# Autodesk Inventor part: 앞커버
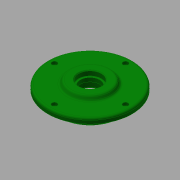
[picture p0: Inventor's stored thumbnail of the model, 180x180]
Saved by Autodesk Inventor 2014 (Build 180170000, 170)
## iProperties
Created: 2016-11
Part Number: 앞커버
Material: 일반
Document SubType Name: Modeling
Designer: mduedu
Density: 1 g/cm^3
Appearance: 진녹색
Mass: 188.69 g
Surface Area: 365.029 cm^2
Volume: 188.69 cm^3
Author: mduedu
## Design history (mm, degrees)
sketch "스케치1"
  geometry: L1 (28.5, -17.5)-(28.5, -30); L2 (28.5, -30)-(22.5, -33.464); L3 (22.5, -33.464)-(22.5, -65); L4 (22.5, -65)-(14.5, -65); L5 (14.5, -65)-(14.5, -47.5); L6 (14.5, -47.5)-(0, -47.5); L7 (0, -47.5)-(0, -23.5); L8 (0, 0)-(28.5, 0); L9 (14.5, -23.5)-(14.5, -15); L10 (14.5, -15)-(20.5, -15); L11 (20.5, -15)-(20.5, -17.5); L12 (0, -23.5)-(14.5, -23.5); L13 (20.5, -17.5)-(28.5, -17.5)
  constraints: 26 end point, 8 parallel, 3 perpendicular, 2 horizontal, 2 vertical alignment, 1 collinear
  dimensions: "d0" = 14.5 distance of L5.end L6.end; "d2" = 8 distance of L3.end L4.end; "d3" = 6 distance between parallel lines of L1 L3; "d4" = 120 deg angle of L3 L2; "d5" = 8 distance of L11.end L1.start; "d6" = 60 diameter of L1.end L8; "d7" = 30 diameter of L10 L8; "d8" = 47 diameter of L12 L8; "d9" = 35 diameter of L13 L8; "d10" = 95 diameter of L6 L8; "d11" = 130 diameter of L4 L8
revolve "회전1" sketch "스케치1" stored, may be unused: angle "d12" = 90 deg
fillet "모깎기1" dims "d13" = 0.5
fillet "모깎기2" dims "d14" = 3
chamfer "모따기1" distance "d15" = 1; stored, may be unused: second distance "d16" = 2, angle "d17" = 45 deg
fillet "모깎기3" dims "d18" = 0.3
sketch "스케치2" dims "d19" = 110
  geometry: 6 further points
  constraints: 2 vertical alignment, 1 coincident, 7 other
  dimensions: "d22" = 360 deg dimension on point (0, 0) point (0, 55) (derived)
sketch "스케치3"
  geometry: 4 further points
  constraints: 4 other
hole "구멍1" sketch "스케치3" at (0, 55), (-55, 0), (55, 0), (0, -55) diameter "d24" = 4.5; stored, may be unused: countersink angle "d28" = 90 deg, drill point angle "d30" = 0 deg; dims "d25" = 6, "d26" = 8, "d27" = 4.6, "d29" = 8
node "솔리드1"
